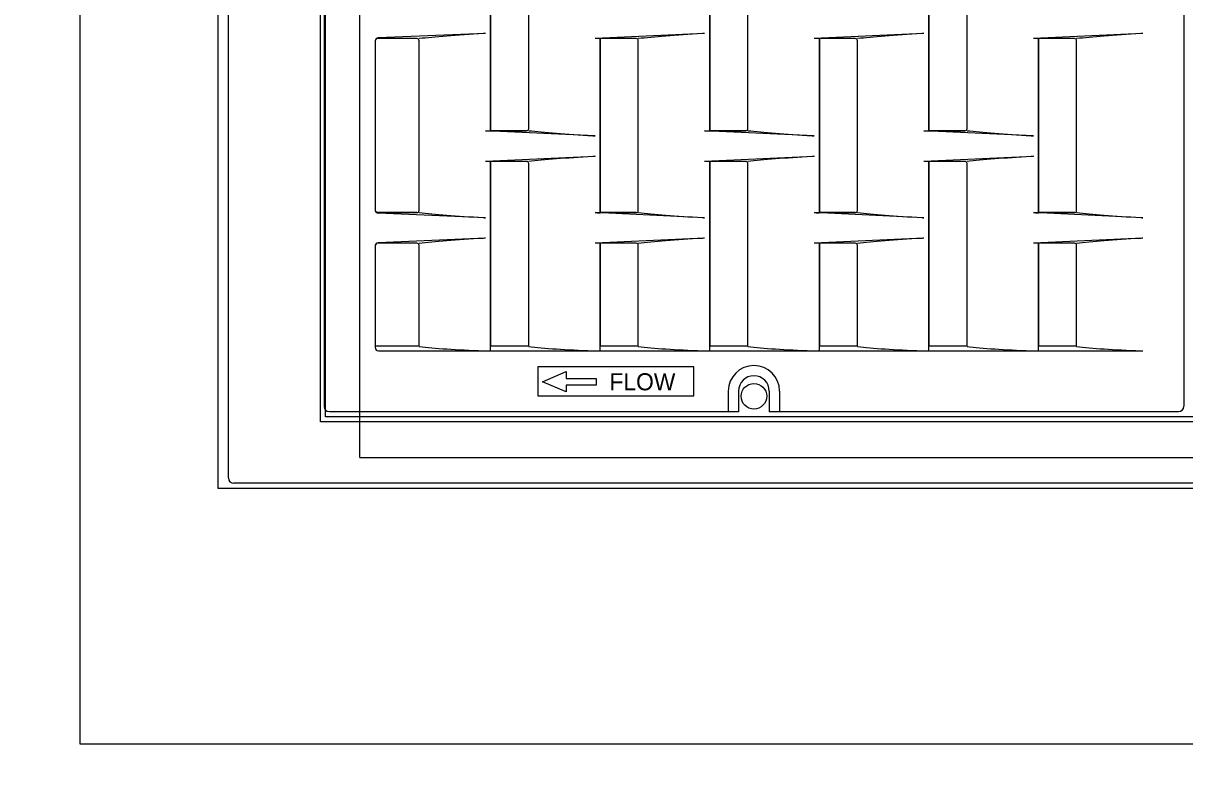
# Model space of a CAD drawing. Extents: x 99862 to 103151, y 100000 to 102076.
# Drawn here: x 101243.1 to 101385.1, y 101533.5 to 101624.9 of the extents above; entities that cross this region are included whole.
import ezdxf

# ---------------------------------------------------------------- set-up
doc = ezdxf.new("R2010")
doc.units = 0
for name, color, linetype in [('Level 1', 7, 'Continuous'), ('Level 10', 7, 'Continuous'), ('Level 11', 7, 'Continuous'), ('Level 2', 7, 'Continuous'), ('Level 20', 7, 'Continuous'), ('Level 5', 7, 'Continuous'), ('Level 7', 7, 'Continuous')]:
    doc.layers.add(name, color=color, linetype=linetype)

msp = doc.modelspace()

# ---------------------------------------------------------------- linework, layer by layer
at = {"layer": 'Level 1'}
for points in [[(101490.72, 101576.22), (101279.47, 101576.22), (101279.47, 101682.47), (101490.72, 101682.47)], [(101490.1, 101576.85), (101280.1, 101576.85), (101280.1, 101681.85), (101490.1, 101681.85)]]:
    msp.add_lwpolyline(points, close=True, dxfattribs=at)
msp.add_circle((101332.44, 101579.35), 1.56, dxfattribs=at)
at = {"layer": 'Level 10'}
for q in [(101284.28, 101686.85), (101486.78, 101571.85)]:
    msp.add_line((101284.28, 101571.85), q, dxfattribs=at)
for points in [[(101300.26, 101633.06), (101300.26, 101611.8), (101304.66, 101611.8)], [(101304.92, 101612.06), (101304.92, 101632.8)], [(101327.05, 101633.06), (101327.05, 101611.8), (101331.44, 101611.8)], [(101331.7, 101612.06), (101331.7, 101632.8)], [(101353.83, 101633.06), (101353.83, 101611.8), (101358.23, 101611.8)], [(101358.49, 101612.06), (101358.49, 101632.8)], [(101286.15, 101622.74), (101286.15, 101602.11)], [(101291.26, 101623.06), (101286.31, 101623.06)], [(101291.52, 101602.05), (101291.52, 101622.8)], [(101313.65, 101623.06), (101313.65, 101601.79), (101318.05, 101601.79)], [(101318.05, 101623.06), (101313.65, 101623.06)], [(101318.31, 101602.05), (101318.31, 101622.8)], [(101340.44, 101623.06), (101340.44, 101601.79), (101344.83, 101601.79)], [(101344.83, 101623.06), (101340.44, 101623.06)], [(101345.1, 101602.05), (101345.1, 101622.8)], [(101367.22, 101623.06), (101367.22, 101601.79), (101371.62, 101601.79)], [(101371.62, 101623.06), (101367.22, 101623.06)], [(101371.88, 101602.05), (101371.88, 101622.8)], [(101300.26, 101608.05), (101300.26, 101585.53), (101304.92, 101585.53), (101304.92, 101607.79)], [(101304.66, 101608.05), (101300.26, 101608.05)], [(101327.05, 101608.05), (101327.05, 101585.53), (101331.7, 101585.53), (101331.7, 101607.79)], [(101331.44, 101608.05), (101327.05, 101608.05)], [(101353.83, 101608.05), (101353.83, 101585.53), (101358.49, 101585.53), (101358.49, 101607.79)], [(101358.23, 101608.05), (101353.83, 101608.05)], [(101286.31, 101601.79), (101291.26, 101601.79)], [(101286.15, 101597.72), (101286.15, 101585.53), (101291.52, 101585.53), (101291.52, 101587.17), (101291.52, 101597.78)], [(101291.26, 101598.04), (101286.31, 101598.04)], [(101313.65, 101598.04), (101313.65, 101585.53), (101318.31, 101585.53), (101318.31, 101597.78)], [(101318.05, 101598.04), (101313.65, 101598.04)], [(101340.44, 101598.04), (101340.44, 101585.53), (101345.1, 101585.53), (101345.1, 101597.78)], [(101344.83, 101598.04), (101340.44, 101598.04)], [(101367.22, 101598.04), (101367.22, 101585.53), (101371.88, 101585.53), (101371.88, 101597.78)], [(101371.62, 101598.04), (101367.22, 101598.04)]]:
    msp.add_lwpolyline(points, dxfattribs=at)
for centre, radius, start, end in [((101286.54, 101622.74), 0.391, 125.8762, 180), ((101291.26, 101622.8), 0.261, 360, 90), ((101318.05, 101622.8), 0.261, 360, 90), ((101344.83, 101622.8), 0.261, 360, 90), ((101371.62, 101622.8), 0.261, 360, 90), ((101304.66, 101612.06), 0.261, 270, 0), ((101331.44, 101612.06), 0.261, 270, 0), ((101358.23, 101612.06), 0.261, 270, 0), ((101304.66, 101607.79), 0.261, 360, 90), ((101331.44, 101607.79), 0.261, 360, 90), ((101358.23, 101607.79), 0.261, 360, 90), ((101286.54, 101602.11), 0.391, 180, 234.1238), ((101291.26, 101602.05), 0.261, 270, 0), ((101318.05, 101602.05), 0.261, 270, 0), ((101344.83, 101602.05), 0.261, 270, 0), ((101371.62, 101602.05), 0.261, 270, 0), ((101286.54, 101597.72), 0.391, 125.8762, 180), ((101291.26, 101597.78), 0.261, 0, 90), ((101318.05, 101597.78), 0.261, 360, 90), ((101344.83, 101597.78), 0.261, 360, 90), ((101371.62, 101597.78), 0.261, 360, 90)]:
    msp.add_arc(centre, radius, start, end, dxfattribs=at)
at = {"layer": 'Level 11'}
for p, q in [((101329.31, 101579.98), (101329.31, 101577.47)), ((101330.56, 101579.98), (101330.56, 101577.47)), ((101334.32, 101579.98), (101334.32, 101577.47)), ((101335.57, 101579.98), (101335.57, 101577.47))]:
    msp.add_line(p, q, dxfattribs=at)
msp.add_lwpolyline([(101306.03, 101582.96), (101306.03, 101579.41), (101325.09, 101579.41), (101325.09, 101582.96)], close=True, dxfattribs=at)
msp.add_lwpolyline([(101309.48, 101582.36), (101309.48, 101581.54), (101313.18, 101581.54), (101313.18, 101580.72), (101309.48, 101580.72), (101309.48, 101579.9), (101306.61, 101581.13), (101309.48, 101582.36)], dxfattribs=at)
for radius in [3.13, 1.88]:
    msp.add_arc((101332.44, 101579.98), radius, 360, 180, dxfattribs=at)
at = {"layer": 'Level 2'}
for p, q in [((101300.26, 101611.79), (101300.26, 101633.07)), ((101304.92, 101612.06), (101304.92, 101632.8)), ((101327.05, 101611.79), (101327.05, 101633.07)), ((101331.7, 101612.06), (101331.7, 101632.8)), ((101353.83, 101611.79), (101353.83, 101633.07)), ((101358.49, 101612.06), (101358.49, 101632.8)), ((101279.9, 101628.1), (101279.9, 101578.13)), ((101384.99, 101628.1), (101384.99, 101578.13)), ((101299.63, 101623.68), (101286.52, 101623.13)), ((101326.42, 101623.68), (101313.03, 101623.06)), ((101353.21, 101623.68), (101339.81, 101623.06)), ((101379.99, 101623.68), (101366.6, 101623.06)), ((101286.15, 101622.74), (101286.15, 101602.11)), ((101291.26, 101623.06), (101286.31, 101623.06)), ((101291.52, 101602.05), (101291.52, 101622.8)), ((101318.05, 101623.06), (101313.65, 101623.06)), ((101313.65, 101601.79), (101313.65, 101623.06)), ((101318.31, 101602.05), (101318.31, 101622.8)), ((101344.83, 101623.06), (101340.44, 101623.06)), ((101340.44, 101601.79), (101340.44, 101623.06)), ((101345.1, 101602.05), (101345.1, 101622.8)), ((101371.62, 101623.06), (101367.22, 101623.06)), ((101367.22, 101601.79), (101367.22, 101623.06)), ((101371.88, 101602.05), (101371.88, 101622.8)), ((101313.03, 101611.17), (101299.63, 101611.8)), ((101304.66, 101611.8), (101300.26, 101611.8)), ((101339.81, 101611.17), (101326.42, 101611.8)), ((101331.44, 101611.8), (101327.05, 101611.8)), ((101366.6, 101611.17), (101353.21, 101611.8)), ((101358.23, 101611.8), (101353.83, 101611.8)), ((101313.03, 101608.67), (101299.63, 101608.05)), ((101300.26, 101584.95), (101300.26, 101608.05)), ((101304.66, 101608.05), (101300.26, 101608.05)), ((101339.81, 101608.67), (101326.42, 101608.05)), ((101327.05, 101584.95), (101327.05, 101608.05)), ((101331.44, 101608.05), (101327.05, 101608.05)), ((101366.6, 101608.67), (101353.21, 101608.05)), ((101353.83, 101584.95), (101353.83, 101608.05)), ((101358.23, 101608.05), (101353.83, 101608.05)), ((101304.92, 101585.53), (101304.92, 101607.79)), ((101331.7, 101585.53), (101331.7, 101607.79)), ((101358.49, 101585.53), (101358.49, 101607.79)), ((101291.26, 101601.79), (101286.31, 101601.79)), ((101299.63, 101601.17), (101286.52, 101601.72)), ((101326.42, 101601.17), (101313.03, 101601.79)), ((101318.05, 101601.79), (101313.65, 101601.79)), ((101353.21, 101601.17), (101339.81, 101601.79)), ((101344.83, 101601.79), (101340.44, 101601.79)), ((101379.99, 101601.17), (101366.6, 101601.79)), ((101371.62, 101601.79), (101367.22, 101601.79)), ((101299.63, 101598.66), (101286.52, 101598.11)), ((101326.42, 101598.66), (101313.03, 101598.04)), ((101353.21, 101598.66), (101339.81, 101598.04)), ((101379.99, 101598.66), (101366.6, 101598.04)), ((101286.15, 101597.72), (101286.15, 101585.3)), ((101291.26, 101598.04), (101286.31, 101598.04)), ((101291.52, 101587.17), (101291.52, 101597.78)), ((101313.65, 101584.95), (101313.65, 101598.04)), ((101318.05, 101598.04), (101313.65, 101598.04)), ((101318.31, 101585.53), (101318.31, 101597.78)), ((101340.44, 101584.95), (101340.44, 101598.04)), ((101344.83, 101598.04), (101340.44, 101598.04)), ((101345.1, 101585.53), (101345.1, 101597.78)), ((101367.22, 101584.95), (101367.22, 101598.04)), ((101371.62, 101598.04), (101367.22, 101598.04)), ((101371.88, 101585.53), (101371.88, 101597.78)), ((101291.52, 101585.53), (101291.52, 101587.17)), ((101286.15, 101585.53), (101291.52, 101585.53)), ((101291.52, 101585.46), (101291.52, 101585.53)), ((101300.26, 101585.53), (101304.92, 101585.53)), ((101304.92, 101585.46), (101304.92, 101585.53)), ((101313.65, 101585.53), (101318.31, 101585.53)), ((101318.31, 101585.46), (101318.31, 101585.53)), ((101327.05, 101585.53), (101331.7, 101585.53)), ((101331.7, 101585.46), (101331.7, 101585.53)), ((101340.44, 101585.53), (101345.1, 101585.53)), ((101345.1, 101585.46), (101345.1, 101585.53)), ((101353.83, 101585.53), (101358.49, 101585.53)), ((101358.49, 101585.46), (101358.49, 101585.53)), ((101367.22, 101585.53), (101371.88, 101585.53)), ((101371.88, 101585.46), (101371.88, 101585.53)), ((101286.54, 101584.9), (101379.98, 101584.9)), ((101330.56, 101577.47), (101280.55, 101577.47)), ((101384.33, 101577.47), (101334.32, 101577.47))]:
    msp.add_line(p, q, dxfattribs=at)
for points in [[(101268.22, 101569.37), (101268.22, 101689.32)], [(101501.32, 101568.72), (101268.87, 101568.72)]]:
    msp.add_lwpolyline(points, dxfattribs=at)
for centre, radius, start, end in [((101286.54, 101622.74), 0.391, 92.6026, 180), ((101291.26, 101622.8), 0.261, 0, 90), ((101318.05, 101622.8), 0.261, 0, 90), ((101344.83, 101622.8), 0.261, 0, 90), ((101371.62, 101622.8), 0.261, 0, 90), ((101304.66, 101612.06), 0.261, 270, 0), ((101331.44, 101612.06), 0.261, 270, 0), ((101358.23, 101612.06), 0.261, 270, 0), ((101304.66, 101607.79), 0.261, 0, 90), ((101331.44, 101607.79), 0.261, 0, 90), ((101358.23, 101607.79), 0.261, 0, 90), ((101286.54, 101602.11), 0.391, 180, 267.3974), ((101291.26, 101602.05), 0.261, 270, 0), ((101318.05, 101602.05), 0.261, 270, 0), ((101344.83, 101602.05), 0.261, 270, 0), ((101371.62, 101602.05), 0.261, 270, 0), ((101286.54, 101597.72), 0.391, 92.6026, 180), ((101291.26, 101597.78), 0.261, 0, 90), ((101318.05, 101597.78), 0.261, 0, 90), ((101344.83, 101597.78), 0.261, 0, 90), ((101371.62, 101597.78), 0.261, 0, 90), ((101286.54, 101585.3), 0.391, 180, 270), ((101280.55, 101578.13), 0.652, 180, 270), ((101384.33, 101578.13), 0.652, 270, 0), ((101268.87, 101569.37), 0.652, 180, 270)]:
    msp.add_arc(centre, radius, start, end, dxfattribs=at)
for centre, major_axis, ratio, start_param, end_param in [((101306.66, 101623.43), (17.51, 0.8), 0.035758, 1.997966, 2.612379), ((101299.63, 101623.66), (0.625, 0.028), 0.035758, 1.569169, 1.997966), ((101333.44, 101623.43), (17.51, 0.8), 0.035758, 1.997966, 2.612379), ((101326.42, 101623.66), (0.625, 0.028), 0.035758, 1.569169, 1.997966), ((101360.23, 101623.43), (17.51, 0.8), 0.035758, 1.997966, 2.612379), ((101353.21, 101623.66), (0.625, 0.028), 0.035758, 1.569169, 1.997966), ((101387.01, 101623.43), (17.51, 0.8), 0.035758, 1.997966, 2.612379), ((101379.99, 101623.66), (0.625, 0.028), 0.035758, 1.569169, 1.997966), ((101313.03, 101623.03), (0.625, 0.028), 0.035758, 6.281558, 7.852354), ((101339.81, 101623.03), (0.625, 0.028), 0.035758, 6.281558, 7.852354), ((101366.6, 101623.03), (0.625, 0.028), 0.035758, 6.281558, 7.852354), ((101299.63, 101611.82), (-0.625, 0.028), 0.035758, 1.572424, 3.14322), ((101320.05, 101611.43), (-17.51, 0.8), 0.035758, 0.529214, 1.143627), ((101313.03, 101611.2), (-0.625, 0.028), 0.035758, 1.143627, 1.572424), ((101326.42, 101611.82), (-0.625, 0.028), 0.035758, 1.572424, 3.14322), ((101346.83, 101611.43), (-17.51, 0.8), 0.035758, 0.529214, 1.143627), ((101339.81, 101611.2), (-0.625, 0.028), 0.035758, 1.143627, 1.572424), ((101353.21, 101611.82), (-0.625, 0.028), 0.035758, 1.572424, 3.14322), ((101373.62, 101611.43), (-17.51, 0.8), 0.035758, 0.529214, 1.143627), ((101366.6, 101611.2), (-0.625, 0.028), 0.035758, 1.143627, 1.572424), ((101299.63, 101608.02), (0.625, 0.028), 0.035758, 6.281558, 7.852354), ((101320.05, 101608.42), (17.51, 0.8), 0.035758, 1.997966, 2.612379), ((101313.03, 101608.65), (0.625, 0.028), 0.035758, 1.569169, 1.997966), ((101326.42, 101608.02), (0.625, 0.028), 0.035758, 6.281558, 7.852354), ((101346.83, 101608.42), (17.51, 0.8), 0.035758, 1.997966, 2.612379), ((101339.81, 101608.65), (0.625, 0.028), 0.035758, 1.569169, 1.997966), ((101353.21, 101608.02), (0.625, 0.028), 0.035758, 6.281558, 7.852354), ((101373.62, 101608.42), (17.51, 0.8), 0.035758, 1.997966, 2.612379), ((101366.6, 101608.65), (0.625, 0.028), 0.035758, 1.569169, 1.997966), ((101306.66, 101601.42), (-17.51, 0.8), 0.035758, 0.529214, 1.143627), ((101299.63, 101601.19), (-0.625, 0.028), 0.035758, 1.143627, 1.572424), ((101313.03, 101601.81), (-0.625, 0.028), 0.035758, 1.572424, 3.14322), ((101333.44, 101601.42), (-17.51, 0.8), 0.035758, 0.529214, 1.143627), ((101326.42, 101601.19), (-0.625, 0.028), 0.035758, 1.143627, 1.572424), ((101339.81, 101601.81), (-0.625, 0.028), 0.035758, 1.572424, 3.14322), ((101360.23, 101601.42), (-17.51, 0.8), 0.035758, 0.529214, 1.143627), ((101353.21, 101601.19), (-0.625, 0.028), 0.035758, 1.143627, 1.572424), ((101366.6, 101601.81), (-0.625, 0.028), 0.035758, 1.572424, 3.14322), ((101387.01, 101601.42), (-17.51, 0.8), 0.035758, 0.529214, 1.143627), ((101379.99, 101601.19), (-0.625, 0.028), 0.035758, 1.143627, 1.572424), ((101306.66, 101598.41), (17.51, 0.8), 0.035758, 1.997966, 2.612379), ((101299.63, 101598.64), (0.625, 0.028), 0.035758, 1.569169, 1.997966), ((101333.44, 101598.41), (17.51, 0.8), 0.035758, 1.997966, 2.612379), ((101326.42, 101598.64), (0.625, 0.028), 0.035758, 1.569169, 1.997966), ((101360.23, 101598.41), (17.51, 0.8), 0.035758, 1.997966, 2.612379), ((101353.21, 101598.64), (0.625, 0.028), 0.035758, 1.569169, 1.997966), ((101387.01, 101598.41), (17.51, 0.8), 0.035758, 1.997966, 2.612379), ((101379.99, 101598.64), (0.625, 0.028), 0.035758, 1.569169, 1.997966), ((101313.03, 101598.02), (0.625, 0.028), 0.035758, 6.281558, 7.852354), ((101339.81, 101598.02), (0.625, 0.028), 0.035758, 6.281558, 7.852354), ((101366.6, 101598.02), (0.625, 0.028), 0.035758, 6.281558, 7.852354), ((101306.66, 101586.13), (-17.51, 0), 0.076923, 0.527586, 1.142), ((101320.05, 101586.13), (-17.51, 0), 0.076923, 0.527586, 1.142), ((101333.44, 101586.13), (-17.51, 0), 0.076923, 0.527586, 1.142), ((101346.83, 101586.13), (-17.51, 0), 0.076923, 0.527586, 1.142), ((101360.23, 101586.13), (-17.51, 0), 0.076923, 0.527586, 1.142), ((101373.62, 101586.13), (-17.51, 0), 0.076923, 0.527586, 1.142), ((101387.01, 101586.13), (-17.51, 0), 0.076923, 0.527586, 1.142), ((101299.63, 101584.95), (-0.625, 0), 0.076923, 1.142, 1.570796), ((101299.63, 101584.95), (-0.625, 0), 0.076923, 1.570796, 3.141593), ((101313.03, 101584.95), (-0.625, 0), 0.076923, 1.142, 1.570796), ((101313.03, 101584.95), (-0.625, 0), 0.076923, 1.570796, 3.141593), ((101326.42, 101584.95), (-0.625, 0), 0.076923, 1.142, 1.570796), ((101326.42, 101584.95), (-0.625, 0), 0.076923, 1.570796, 3.141593), ((101339.81, 101584.95), (-0.625, 0), 0.076923, 1.142, 1.570796), ((101339.81, 101584.95), (-0.625, 0), 0.076923, 1.570796, 3.141593), ((101353.21, 101584.95), (-0.625, 0), 0.076923, 1.142, 1.570796), ((101353.21, 101584.95), (-0.625, 0), 0.076923, 1.570796, 3.141593), ((101366.6, 101584.95), (-0.625, 0), 0.076923, 1.142, 1.570796), ((101366.6, 101584.95), (-0.625, 0), 0.076923, 1.570796, 3.141593), ((101379.98, 101584.95), (-0.625, 0), 0.076923, 1.142, 1.570796), ((101379.99, 101584.95), (-0.625, 0), 0.076923, 1.142, 1.570796)]:
    msp.add_ellipse(centre, major_axis=major_axis, ratio=ratio, start_param=start_param, end_param=end_param, dxfattribs=at)
at = {"layer": 'Level 5'}
for radius in [280, 260, 240]:
    msp.add_circle((101385.1, 101629.35), radius, dxfattribs=at)
at = {"layer": 'Level 7'}
for p, q in [((101250.1, 101536.85), (101250.1, 101721.85)), ((101266.97, 101568.1), (101266.97, 101690.6)), ((101503.22, 101568.1), (101266.97, 101568.1)), ((101520.1, 101536.85), (101250.1, 101536.85))]:
    msp.add_line(p, q, dxfattribs=at)

# ---------------------------------------------------------------- texts
at = {"layer": 'Level 20'}
msp.add_text('FLOW', height=2.087, dxfattribs=at).set_placement((101314.78, 101580.08))

doc.saveas('drawing.dxf')
